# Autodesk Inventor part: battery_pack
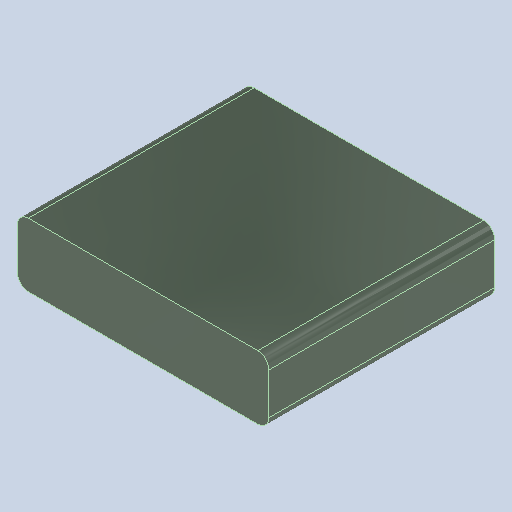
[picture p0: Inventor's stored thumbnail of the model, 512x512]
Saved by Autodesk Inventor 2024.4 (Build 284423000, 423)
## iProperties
Created: 2025-07
Part Number: battery_pack
Material: Generic
Document SubType Name: Modeling
Designer: AdminForWorker
Density: 1 g/cm^3
Appearance: Default
Title: battery_pack v2
Author: AdminForWorker
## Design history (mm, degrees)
feature "Body1"
body "Solid1"
